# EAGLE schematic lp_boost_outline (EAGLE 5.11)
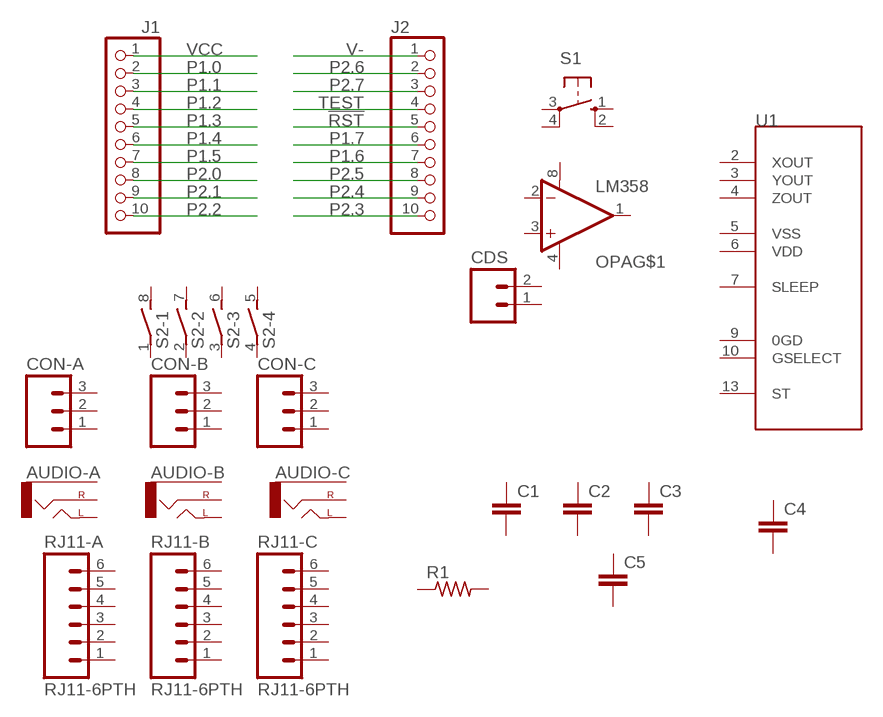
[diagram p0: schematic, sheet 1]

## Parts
AUDIO-A  AUDIO-JACKPTH  [AUDIO-JACK]
AUDIO-B  AUDIO-JACKPTH  [AUDIO-JACK]
AUDIO-C  AUDIO-JACKPTH  [AUDIO-JACK]
C1  CAPPTH1  [CAP-PTH-5MM]
C2  CAPPTH1  [CAP-PTH-5MM]
C3  CAPPTH1  [CAP-PTH-5MM]
C4  CAPPTH1  [CAP-PTH-5MM]
C5  CAP0603-CAP  [0603-CAP]
CDS  M02PTH  [1X02]
CON-A  M03POLAR  [MOLEX-1X3]
CON-B  M03POLAR  [MOLEX-1X3]
CON-C  M03POLAR  [MOLEX-1X3]
J1  PH1X10OCT076  [PH1X10OCT76]
J2  PH1X10OCT076  [PH1X10OCT76]
OPA  LM358  [DIP08]
R1  R-US_0414/5V  [0414V]
RJ11-A  RJ11-6PTH  [RJ11-6]
RJ11-B  RJ11-6PTH  [RJ11-6]
RJ11-C  RJ11-6PTH  [RJ11-6]
S1  40-XX  [B3F-40XX]
S2  DIP04S  [DIP04S]
U1  MMA7361  [LGA14]

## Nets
!RST: J2.5
P1.0: J1.2
P1.1: J1.3
P1.2: J1.4
P1.3: J1.5
P1.4: J1.6
P1.5: J1.7
P1.6: J2.7
P1.7: J2.6
P2.0: J1.8
P2.1: J1.9
P2.2: J1.10
P2.3: J2.10
P2.4: J2.9
P2.5: J2.8
P2.6: J2.2
P2.7: J2.3
TEST: J2.4
V-: J2.1
VCC: J1.1
Unconnected: AUDIO-A.RING(RIGHT) AUDIO-A.SLEEVE AUDIO-A.TIP(LEFT) AUDIO-B.RING(RIGHT) AUDIO-B.SLEEVE AUDIO-B.TIP(LEFT) AUDIO-C.RING(RIGHT) AUDIO-C.SLEEVE AUDIO-C.TIP(LEFT) C1.1 C1.2 C2.1 C2.2 C3.1 C3.2 C4.1 C4.2 C5.1 C5.2 CDS.1 CDS.2 CON-A.1 CON-A.2 CON-A.3 CON-B.1 CON-B.2 CON-B.3 CON-C.1 CON-C.2 CON-C.3 OPA.1(OUT) OPA.2(-IN) OPA.3(+IN) OPA.5(+IN) OPA.6(-IN) OPA.7(OUT) R1.1 R1.2 RJ11-A.1 RJ11-A.2 RJ11-A.3 RJ11-A.4 RJ11-A.5 RJ11-A.6 RJ11-B.1 RJ11-B.2 RJ11-B.3 RJ11-B.4 RJ11-B.5 RJ11-B.6 RJ11-C.1 RJ11-C.2 RJ11-C.3 RJ11-C.4 RJ11-C.5 RJ11-C.6 S1.1(S) S1.2(S1) S1.3(P) S1.4(P1) S2.1 S2.2 S2.3 S2.4 S2.5 S2.6 S2.7 S2.8 U1.2(XOUT) U1.3(YOUT) U1.4(ZOUT) U1.5(VSS) U1.6(VDD) U1.7(SLEEP) U1.9(0GD) U1.10(GSELECT) U1.13(ST)

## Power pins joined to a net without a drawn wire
V+: OPA.8(V+)
V-: OPA.4(V-)

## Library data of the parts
AUDIO-A AUDIO-B AUDIO-C = SparkFun:AUDIO-JACK: 3.5mm Audio Jack Simple 3.5mm common PCB mount audio jack. SKU: PRT-08032
C1-C5 = SparkFun:CAP: Capacitor
CDS = SparkFun:M02: Header 2
CON-A CON-B CON-C = SparkFun:M03: Header 3 Standard 3-pin 0.1" header. Use with straight break away headers (SKU : PRT-00116), right angle break away headers (PRT-00553), swiss pins (PRT-00743), machine pins (PRT-00117), and female headers (PRT-00115). Molex polarized connector foot print use with SKU : PRT-08232 with associated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
J1 J2 = MY_CONN:PH1X10
OPA = SparkFun:LM358
R1 = resistor:R-US_: RESISTOR, American symbol
RJ11-A RJ11-B RJ11-C = SparkFun:RJ11-6: RJ11 Jack Simple 6 pin RJ11 jack. Commonly found on CAT3 devices and Microchip programmers. SKU: PRT-00132
S1 = switch-omron:40-XX: OMRON SWITCH; MF: OMRON COMPONENTS USA; MPN: B3F-4000; OC_FARNELL: 176434; OC_NEWARK: 36K3105
S2 = switch-dil:DIP04S: DIL/CODE SWITCH; OC_FARNELL: unknown; OC_NEWARK: unknown
U1 = SparkFun:MMA7361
